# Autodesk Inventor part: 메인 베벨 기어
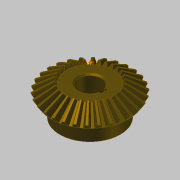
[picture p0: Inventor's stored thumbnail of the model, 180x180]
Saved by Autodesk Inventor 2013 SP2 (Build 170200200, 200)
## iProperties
Created: 2016-04
Part Number: 메인 베벨 기어
Material: 강철, 탄소
Document SubType Name: Modeling
Designer: mdu
Categories: <?xml version="1.0" encoding="UTF-16"?> <MemberInstance><Categories><FamilyTemplate><FamilyTemplateParameter ValueType="xs:double" Id="1" ObjectReferenceKey="da
Mass: 269.926 g
Surface Area: 108.837 cm^2
Volume: 34.2981 cm^3
Density: 7.87 g/cm^3
CustomPartVersion: 1
Author: mdu
Revision Number: 1
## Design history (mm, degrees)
node "맨 위 점"
node "메쉬 평면2"
sketch "톱니 본체 스케치"
  geometry: L1 (0, 0)-(28.669, -21.997); L2 (28.669, -21.997)-(31.109, -18.336); L3 (31.109, -18.336)-(0, 0); L4 (30, -20)-(0, 0); L5 (17.219, -13.212)-(18.685, -11.013); L6 (28.669, -21.997)-(17.219, -13.212); L7 (31.109, -18.336)-(18.685, -11.013); L8 (0, -39.387)-(0, 6.564) reference; L9 (0, -20)-(31.109, -20)
  constraints: 16 end point, 4 point on line, 3 perpendicular, 2 collinear, 1 horizontal alignment, 1 vertical alignment
  dimensions: "d0" = 60 diameter of L4.start L8 (= da_de); "d1" = 57.33744 diameter of L1.end L8 (= da_dfe); "d2" = 62.2188 diameter of L2.end L8 (= da_dae); "d3" = 14.4 distance between parallel lines of L2 L5 (= da_b); "d4" = 18.3359 vertical distance of L2.end L1.start (= da_ve)
revolve "톱니 본체" sketch "톱니 본체 스케치" stored, may be unused: angle "d5" = 90 deg
node "시작점"
node "톱니 평면"
sketch "시작 스케치"
  geometry: L1 (0, -23.505)-(0, 10.645) reference; L2 (-0.709, -2.928)-(0.709, -2.928); A1 r 19.188 centre (-19.457, -7.014) between (-0.709, -2.928) and (-3.232, 3.229); A2 r 19.188 centre (19.457, -7.014) between (3.232, 3.229) and (0.709, -2.928); A3 r 57.403 centre (0, -54.083) between (3.232, 3.229) and (-3.232, 3.229); 1 further point
  constraints: 6 point on circle, 3 centre point, 3 symmetric about line, 2 end point, 1 coincident, 1 perpendicular, 1 other
  dimensions: "d7" = 19.18795 radius of A1 (= fd_rr); "d8" = 19.45712 horizontal distance of point (0, -54.083) A1.centre (= fd_x); "d9" = 47.06905 vertical distance of point (0, -54.083) A1.centre (= fd_y); "d57" = 57.40327 radius of A3 (= 0.5 x fd_dva + 0.3 x da_he); "d58" = 51.15527 distance from line of A3.centre L2 (= 0.5 x fd_dva - 1.12 x da_he)
node "끝점"
  node "끝 평면"
sketch "3D 스케치 오른쪽"
  node "Helical Curve Right" dims "d65" = 229.90621 (computed from da_dm, da_delta, da_beta), "d66" = 31.5, "d67" = 60 (= da_de), "d68" = -9.82794 (= -da_delta), "d69" = 8.10972 (computed from fd_loft, da_delta)
node "끝 평면 오른쪽"
sketch "끝 스케치 오른쪽"
  geometry: L1 (0, -41.54)-(0, 13.178) reference; L2 (-0.422, -1.69)-(0.422, -1.69); A1 r 11.427 centre (-11.587, -4.123) between (-0.422, -1.69) and (-1.925, 1.977); A2 r 11.427 centre (11.587, -4.123) between (1.925, 1.977) and (0.422, -1.69); A3 r 34.184 centre (0, -32.153) between (1.925, 1.977) and (-1.925, 1.977); 1 further point
  constraints: 6 point on circle, 3 centre point, 3 symmetric about line, 2 end point, 1 coincident, 1 perpendicular, 1 other
  dimensions: "d70" = 11.58699 horizontal distance of A3.centre A1.centre (computed from fd_x, fd_ratio); "d71" = 28.03028 vertical distance of point (0, -32.153) A1.centre (computed from fd_y, fd_ratio); "d72" = 11.4267 radius of A1 (computed from fd_rr, fd_ratio); "d73" = 30.46369 distance from line of point (0, -32.153) L2 (computed from d58, fd_ratio); "d74" = 34.18446 radius of A3 (computed from d57, fd_ratio)
feature "로프트 오른쪽" sketch "끝 스케치 오른쪽" dims "d75" = 0, "d77" = 0, "d79" = 0, "d80" = 90 deg, "d85" = 20, "d92" = 90 deg, "d93" = 90 deg, "da_teethtype" = 0 [user parameter]
sketch "3D 스케치 왼쪽"
  node "Helical Curve Left" dims "d26" = 229.90621 (computed from da_dm, da_delta, da_beta), "d27" = 8.10972 (computed from fd_loft, da_delta), "d28" = 60 (= da_de), "d29" = -9.82794 (= -da_delta)
node "끝 평면 왼쪽"
sketch "끝 스케치 왼쪽" dims "d56" = 10.3728 (derived)
  geometry: L1 (0, -43.753)-(0, 15.405) reference; L2 (-0.422, -1.678)-(0.422, -1.678); A1 r 11.427 centre (-11.587, -4.111) between (-0.422, -1.678) and (-1.925, 1.988); A2 r 11.427 centre (11.587, -4.111) between (1.925, 1.988) and (0.422, -1.678); A3 r 34.184 centre (0, -32.142) between (1.925, 1.988) and (-1.925, 1.988); 2 further points; 1 other entity
  constraints: 6 point on circle, 3 centre point, 3 symmetric about line, 2 end point, 1 coincident, 2 other
  dimensions: "d30" = 11.4267 radius of A1 (computed from fd_rr, fd_ratio); "d31" = 11.58699 horizontal distance of point (0, -32.142) A1.centre (computed from fd_x, fd_ratio); "d32" = 28.03028 vertical distance of A1.centre point (0, -32.142) (computed from fd_y, fd_ratio); "d61" = 34.18446 radius of A3 (computed from d57, fd_ratio); "d62" = 30.46369 distance from line of point (0, -32.142) L2 (computed from d58, fd_ratio)
feature "로프트 왼쪽" sketch "끝 스케치 왼쪽" dims "d35" = 0, "d37" = 0, "d39" = 0, "d40" = 90 deg, "d84" = 10, "d90" = 90 deg, "d91" = 90 deg, "da_teethtype" = 0 [user parameter]
sketch "본체 스케치"
  geometry: L1 (0, -35.038)-(0, -19.531) reference; L2 (28.669, -21.997)-(17.219, -13.212) reference; L3 (17.219, -13.212)-(0, -13.212); L4 (28.669, -21.997)-(0, -21.997)
  constraints: 4 end point, 2 perpendicular, 2 point on line
revolve "본체 고정" sketch "본체 스케치" stored, may be unused: angle "d46" = 90 deg
feature "피치 지름" dims angle "d47" = 90 deg
sketch "스케치8"
  geometry: C1 r 22.5 at (0, 0); 1 further point
  constraints: 1 centre point, 1 coincident
  dimensions: "d94" = 45 diameter of C1
extrude "돌출1" join sketch "스케치8" distance "d95" = 13; taper "d96" = 0 deg
sketch "스케치9"
  geometry: 1 further point
hole "구멍1" sketch "스케치9" at (0, 0) diameter "d97" = 17; stored, may be unused: countersink angle "d101" = 90 deg, drill point angle "d103" = 118 deg; dims "d98" = 6, "d99" = 4, "d100" = 2, "d102" = 8
sketch "스케치10"
  geometry: L1 (8.124, 2.5)-(10.8, 2.5); L2 (10.8, 2.5)-(10.8, -2.5); L3 (10.8, -2.5)-(8.124, -2.5); A1 r 8.5 centre (0, 0) between (8.124, 2.5) and (8.124, -2.5) reference; 1 further point
  constraints: 6 end point, 2 parallel, 2 point on circle, 1 horizontal, 1 perpendicular
  dimensions: "d104" = 5 distance of L1.end L2.end; "d112" = 19.3 dimension on A1 L2
extrude "돌출2" cut sketch "스케치10" stored distance "d106" = 10; taper "d107" = 0 deg
chamfer "모따기1" distance "d108" = 1; stored, may be unused: second distance "d109" = 2, angle "d110" = 45 deg
fillet "모깎기1" dims "d111" = 2
body "Solid1"
feature "로프트" dims "d17" = 0, "d18" = 90 deg, "d19" = 0, "d20" = 90 deg, "d89" = 0, "da_teethtype" = 0 [user parameter]
pattern_circular "원형 패턴" dims angle "d22" = 360 deg, "d88" = 0, "da_teethtype" = 0 [user parameter]
pattern_circular "원형 패턴 오른쪽" dims angle "d82" = 360 deg, "da_teethtype" = 0 [user parameter]
pattern_circular "원형 패턴 왼쪽" dims angle "d42" = 360 deg, "da_teethtype" = 0 [user parameter]
sketch "끝 스케치"
  geometry: L1 (0, -15.359)-(0, 6.983) reference; L2 (-0.422, -1.69)-(0.422, -1.69); A1 r 11.427 centre (-11.587, -4.123) between (-0.422, -1.69) and (-1.925, 1.977); A2 r 11.427 centre (11.587, -4.123) between (1.925, 1.977) and (0.422, -1.69); A3 r 34.184 centre (0, -32.153) between (1.925, 1.977) and (-1.925, 1.977); 1 further point
  constraints: 6 point on circle, 3 centre point, 3 symmetric about line, 2 end point, 1 coincident, 1 other
  dimensions: "d12" = 11.4267 radius of A1 (computed from fd_rr, fd_ratio); "d15" = 11.58699 horizontal distance of A1.centre point (0, -32.153) (computed from fd_x, fd_ratio); "d16" = 28.03028 vertical distance of A1.centre point (0, -32.153) (computed from fd_y, fd_ratio); "d59" = 34.18446 radius of A3 (computed from d57, fd_ratio); "d60" = 30.46369 distance from line of A3.centre L2 (computed from d58, fd_ratio)
sketch "Sketch6"
  geometry: L1 (30, -20)-(0, 0) reference; L2 (0, -37.8)-(0, 6.3) reference
body "Srf1"
other parameters: "da_b" = 14.4 [user parameter; used in 2 equation terms], "da_de" = 60 [user parameter; used in 4 equation terms], "da_dae" = 62.2188 [user parameter; used in 2 equation terms], "da_dfe" = 57.33744 [user parameter; used in 1 equation term], "da_le" = 36.05551 [user parameter; used in 1 equation term], "da_omega" = 90 deg [user parameter; used in 1 equation term], "da_beta" = 0 [user parameter; used in 2 equation terms], "da_delta" = 9.82794 [user parameter; used in 8 equation terms], "da_alpha" = 20 deg [user parameter; used in 2 equation terms], "da_he" = 4.4 [user parameter; used in 4 equation terms], "da_ve" = 18.3359 [user parameter; used in 1 equation term], "fd_dv" = 108.16654 (computed from da_de, da_delta) [user parameter; used in 1 equation term], "fd_dva" = 112.16654 (computed from da_dae, da_delta) [user parameter; used in 3 equation terms], "fd_dvb" = 101.6433 (computed from fd_dv, da_alpha) [user parameter; used in 2 equation terms], "da_zv" = 540.83269 [user parameter; used in 1 equation term], "fd_loft" = 14.62 (= da_b + 0.05 x da_he) [user parameter; used in 4 equation terms], "fd_ratio" = 5.95514 (computed from da_le, fd_loft) [user parameter; used in 15 equation terms], "fd_rr" = 19.18795 (computed from fd_dd, fd_dvb) [user parameter; used in 6 equation terms], "fd_angle" = 0.29367 (computed from da_zv) [user parameter; used in 4 equation terms], "fd_x1" = 1.58802 (computed from da_dvw, fd_angle) [user parameter; used in 1 equation term], "fd_y1" = 54.05995 (computed from da_dvw, fd_angle) [user parameter; used in 1 equation term], "fd_x2" = 17.8691 (computed from fd_rr, fd_angle2, fd_angle) [user parameter; used in 1 equation term], "fd_y2" = 6.9909 (computed from fd_rr, fd_angle2, fd_angle) [user parameter; used in 1 equation term], "fd_x" = 19.45712 (= fd_x1 + fd_x2) [user parameter; used in 4 equation terms], "fd_y" = 47.06905 (= fd_y1 - fd_y2) [user parameter; used in 4 equation terms], "fd_angle2" = 3.43555 (computed from fd_dvb, fd_dd, da_alpha) [user parameter; used in 2 equation terms], "fd_dd" = 108.64654 (= fd_dva - 0.8 x da_he) [user parameter; used in 2 equation terms], "da_dvw" = 108.16654 [user parameter; used in 2 equation terms], "d11" = 14.62 (= fd_loft), "da_dm" = 48.01848 [user parameter; used in 2 equation terms], "da_x" = 0 [user parameter], "da_m" = 2 [user parameter], "d48" = 0, "d49" = 0, "d50" = 90 deg (= da_omega), "d51" = 6 deg (computed from da_z), "d52" = 0, "d53" = 0, "d54" = 0
